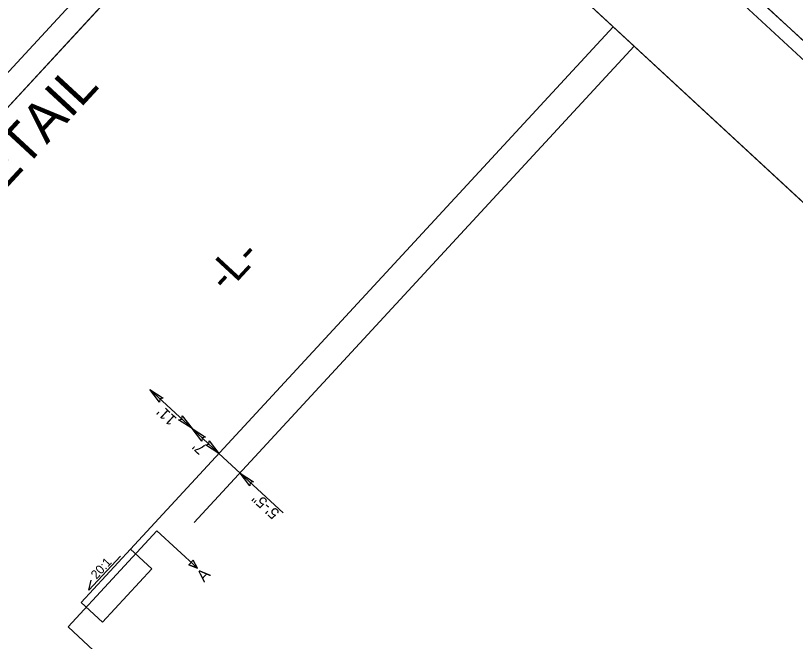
# Model space of a CAD drawing. Extents: x 1768274 to 1769121, y 999922 to 1000687.
# Drawn here: x 1768888.3 to 1769037.2, y 1000133.4 to 1000252.8 of the extents above; entities that cross this region are included whole.
import ezdxf

# ---------------------------------------------------------------- set-up
doc = ezdxf.new("R2010")
doc.units = 0
for name, color, linetype in [('E_NCDOT_Terrain_Model_Boundary', 7, 'Continuous'), ('E_NCDOT_Terrain_Model_Contour_Imported', 7, 'Continuous'), ('E_NCDOT_Terrain_Model_Contour_Major', 7, 'Continuous'), ('E_NCDOT_Terrain_Model_Island', 7, 'Continuous'), ('E_NCDOT_Terrain_Model_Spot_Elevation', 7, 'Continuous'), ('E_NCDOT_Terrain_Model_Triangle_Vertices', 7, 'Continuous'), ('E_NCDOT_Terrain_Model_Triangles', 7, 'Continuous')]:
    doc.layers.add(name, color=color, linetype=linetype)

msp = doc.modelspace()

# ---------------------------------------------------------------- linework, layer by layer
at = {"layer": 'E_NCDOT_Terrain_Model_Boundary'}
msp.add_lwpolyline([(1768900.84, 1000140.8), (1768910.25, 1000150.98), (1768914.29, 1000147.25), (1768904.88, 1000137.07)], close=True, dxfattribs=at)
at = {"layer": 'E_NCDOT_Terrain_Model_Contour_Imported'}
msp.add_lwpolyline([(1768737.29, 1000073.61), (1768947.71, 1000301.25), (1769102.65, 1000158.03), (1768892.23, 999930.38)], close=True, dxfattribs=at)
at = {"layer": 'E_NCDOT_Terrain_Model_Contour_Major'}
for p, q in [((1768961.29, 1000315.94), (1768737.29, 1000073.61)), ((1769116.23, 1000172.72), (1768961.29, 1000315.94)), ((1769102.65, 1000158.03), (1768947.71, 1000301.26))]:
    msp.add_line(p, q, dxfattribs=at)
at = {"layer": 'E_NCDOT_Terrain_Model_Island'}
for p, q in [((1768910.25, 1000150.98), (1769002.41, 1000250.69)), ((1768922.43, 1000156.06), (1769006.45, 1000246.96))]:
    msp.add_line(p, q, dxfattribs=at)
msp.add_lwpolyline([(1768904.88, 1000137.07), (1768900.84, 1000140.8), (1768910.25, 1000150.98)], dxfattribs=at)
at = {"layer": 'E_NCDOT_Terrain_Model_Spot_Elevation'}
msp.add_lwpolyline([(1768729.03, 1000071.31), (1768959.82, 1000320.98), (1769121.37, 1000171.65), (1768890.59, 999921.97)], close=True, dxfattribs=at)
at = {"layer": 'E_NCDOT_Terrain_Model_Triangle_Vertices'}
msp.add_line((1769121.37, 1000171.65), (1768959.82, 1000320.98), dxfattribs=at)
at = {"layer": 'E_NCDOT_Terrain_Model_Triangles'}
for p, q in [((1768921.99, 1000174), (1768913.92, 1000181.47)), ((1768927.13, 1000169.25), (1768921.99, 1000174)), ((1768939.38, 1000157.93), (1768927.13, 1000169.25)), ((1768898.33, 1000136.18), (1768915.26, 1000154.5)), ((1768915.26, 1000154.5), (1768923.01, 1000147.33)), ((1768902.31, 1000143.15), (1768908.34, 1000149.67)), ((1768921.38, 1000148), (1768922.22, 1000148.91)), ((1768923.01, 1000147.33), (1768922.22, 1000148.91)), ((1768923.01, 1000147.33), (1768921.38, 1000148)), ((1768902.31, 1000143.15), (1768902.74, 1000145.05)), ((1768898.33, 1000136.18), (1768906.08, 1000129.01))]:
    msp.add_line(p, q, dxfattribs=at)
for points in [[(1768915.77, 1000179.06), (1768913.92, 1000181.47), (1768916.49, 1000179.81), (1768915.85, 1000179.68)], [(1768920.14, 1000176.42), (1768921.99, 1000174), (1768919.42, 1000175.66), (1768920.06, 1000175.79)], [(1768923.84, 1000171.59), (1768921.99, 1000174), (1768924.57, 1000172.35), (1768923.92, 1000172.22)], [(1768925.28, 1000171.66), (1768927.13, 1000169.25), (1768924.56, 1000170.91), (1768925.2, 1000171.04)], [(1768933.02, 1000163.1), (1768931.17, 1000165.52), (1768933.75, 1000163.86), (1768933.1, 1000163.73)], [(1768921.38, 1000148), (1768923.01, 1000147.33), (1768922.22, 1000148.91)]]:
    msp.add_lwpolyline(points, close=True, dxfattribs=at)

# ---------------------------------------------------------------- texts
at = {"layer": 'E_NCDOT_Terrain_Model_Contour_Major'}
for s, height, p in [('ASPHALT WEDGE DETAIL', 7.5001, (1768820.11, 1000147.91)), ('-L-', 6, (1768928.59, 1000199.75))]:
    msp.add_text(s, height=height, rotation=47.2512, dxfattribs=at).set_placement(p)
at = {"layer": 'E_NCDOT_Terrain_Model_Triangles'}
for s, height, rotation, p in [("11'", 2.131, 137.2513, (1768919.21, 1000175.92)), ("7'", 2.131, 137.2513, (1768924.86, 1000170.4)), ('5\'-5"', 2.131, 137.2513, (1768938.85, 1000158.07)), ('20:1', 1.705, 47.2512, (1768903.75, 1000145.14)), ('A', 2.27, 47.2512, (1768924.28, 1000144.57))]:
    msp.add_text(s, height=height, rotation=rotation, dxfattribs=at).set_placement(p)

doc.saveas('drawing.dxf')
